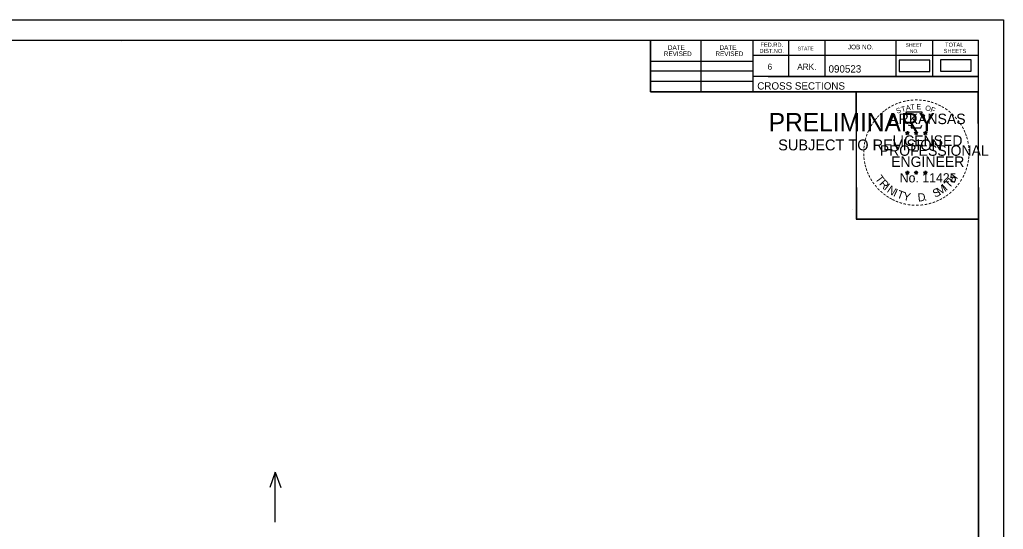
# Model space of a CAD drawing. Extents: x 1406028 to 1412453, y 321733 to 325986.
# Drawn here: x 1411758.3 to 1411946.2, y 322587.7 to 322684.9 of the extents above; entities that cross this region are included whole.
import ezdxf

# ---------------------------------------------------------------- set-up
doc = ezdxf.new("R2010")
doc.units = 0
for name, color, linetype in [('R_Border', 7, 'Continuous'), ('R_Border PE', 7, 'Continuous'), ('R_Border Prem', 7, 'Continuous'), ('R_Fin Surface', 7, 'Continuous'), ('R_No Plot', 7, 'Continuous'), ('R_Water Annot', 7, 'Continuous')]:
    doc.layers.add(name, color=color, linetype=linetype)

msp = doc.modelspace()

# ---------------------------------------------------------------- linework, layer by layer
at = {"layer": 'R_Border'}
for p, q in [((1411625.24, 322681.05), (1411941.42, 322681.05)), ((1411777.76, 322680.79), (1411777.76, 322680.79)), ((1411777.76, 322680.79), (1411777.76, 322680.79)), ((1411878.78, 322671.17), (1411878.78, 322681.05)), ((1411888.46, 322671.17), (1411888.46, 322681.05)), ((1411898.32, 322681.05), (1411898.32, 322671.17)), ((1411905.16, 322681.05), (1411905.16, 322674.11)), ((1411912.1, 322681.05), (1411912.1, 322674.11)), ((1411925.68, 322681.05), (1411925.68, 322674.11)), ((1411932.62, 322681.05), (1411932.62, 322674.11)), ((1411941.42, 322475.59), (1411941.42, 322681.05)), ((1411878.78, 322677.03), (1411898.32, 322677.03)), ((1411941.42, 322678.11), (1411898.32, 322678.11)), ((1411941.42, 322678.13), (1411941.42, 322678.13)), ((1411878.78, 322675.17), (1411898.32, 322675.17)), ((1411878.78, 322673.23), (1411898.32, 322673.23)), ((1411941.42, 322674.11), (1411898.32, 322674.11)), ((1411901.28, 322674.11), (1411941.42, 322674.11)), ((1411941.42, 322671.17), (1411878.78, 322671.17))]:
    msp.add_line(p, q, dxfattribs=at)
at = {"layer": 'R_Border PE'}
for p, q in [((1411927.51, 322663.42), (1411927.86, 322663.31)), ((1411927.51, 322663.42), (1411927.76, 322663.38)), ((1411927.51, 322663.42), (1411927.75, 322663.3)), ((1411927.86, 322663.68), (1411927.82, 322663.43)), ((1411927.86, 322663.31), (1411927.86, 322663.68)), ((1411927.86, 322663.68), (1411927.91, 322663.43)), ((1411928.2, 322663.42), (1411927.86, 322663.31)), ((1411928.2, 322663.42), (1411927.92, 322663.37)), ((1411928.2, 322663.42), (1411928, 322663.32)), ((1411929.18, 322663.42), (1411929.53, 322663.31)), ((1411929.18, 322663.42), (1411929.43, 322663.38)), ((1411929.18, 322663.42), (1411929.42, 322663.3)), ((1411929.53, 322663.68), (1411929.49, 322663.43)), ((1411929.53, 322663.31), (1411929.53, 322663.68)), ((1411929.53, 322663.68), (1411929.58, 322663.43)), ((1411929.87, 322663.42), (1411929.53, 322663.31)), ((1411929.87, 322663.42), (1411929.59, 322663.37)), ((1411929.87, 322663.42), (1411929.67, 322663.32)), ((1411930.94, 322663.41), (1411931.29, 322663.3)), ((1411930.94, 322663.41), (1411931.2, 322663.37)), ((1411930.94, 322663.41), (1411931.18, 322663.29)), ((1411931.29, 322663.67), (1411931.25, 322663.41)), ((1411931.29, 322663.3), (1411931.29, 322663.67)), ((1411931.29, 322663.67), (1411931.34, 322663.42)), ((1411931.64, 322663.41), (1411931.29, 322663.3)), ((1411931.64, 322663.41), (1411931.35, 322663.36)), ((1411931.64, 322663.41), (1411931.43, 322663.31)), ((1411927.64, 322663.02), (1411927.86, 322663.31)), ((1411927.64, 322663.02), (1411927.77, 322663.26)), ((1411927.64, 322663.02), (1411927.86, 322663.23)), ((1411928.07, 322663.02), (1411927.86, 322663.31)), ((1411928.07, 322663.02), (1411927.86, 322663.23)), ((1411928.07, 322663.02), (1411927.93, 322663.31)), ((1411929.31, 322663.02), (1411929.53, 322663.31)), ((1411929.31, 322663.02), (1411929.44, 322663.26)), ((1411929.31, 322663.02), (1411929.53, 322663.23)), ((1411929.74, 322663.02), (1411929.53, 322663.31)), ((1411929.74, 322663.02), (1411929.53, 322663.23)), ((1411929.74, 322663.02), (1411929.6, 322663.31)), ((1411931.08, 322663), (1411931.29, 322663.3)), ((1411931.08, 322663), (1411931.2, 322663.25)), ((1411931.08, 322663), (1411931.29, 322663.22)), ((1411931.5, 322663), (1411931.29, 322663.3)), ((1411931.5, 322663), (1411931.29, 322663.22)), ((1411931.5, 322663), (1411931.37, 322663.29)), ((1411927.5, 322655.85), (1411927.85, 322655.74)), ((1411927.5, 322655.85), (1411927.76, 322655.81)), ((1411927.5, 322655.85), (1411927.74, 322655.73)), ((1411927.85, 322656.1), (1411927.81, 322655.85)), ((1411927.85, 322655.74), (1411927.85, 322656.1)), ((1411927.85, 322656.1), (1411927.9, 322655.85)), ((1411928.2, 322655.85), (1411927.85, 322655.74)), ((1411928.2, 322655.85), (1411927.91, 322655.8)), ((1411928.2, 322655.85), (1411928, 322655.75)), ((1411929.17, 322655.85), (1411929.52, 322655.74)), ((1411929.17, 322655.85), (1411929.43, 322655.81)), ((1411929.17, 322655.85), (1411929.41, 322655.73)), ((1411929.52, 322656.1), (1411929.48, 322655.85)), ((1411929.52, 322655.74), (1411929.52, 322656.1)), ((1411929.52, 322656.1), (1411929.57, 322655.85)), ((1411929.87, 322655.85), (1411929.52, 322655.74)), ((1411929.87, 322655.85), (1411929.58, 322655.8)), ((1411929.87, 322655.85), (1411929.67, 322655.75)), ((1411930.94, 322655.84), (1411931.29, 322655.73)), ((1411930.94, 322655.84), (1411931.19, 322655.8)), ((1411930.94, 322655.84), (1411931.18, 322655.72)), ((1411931.29, 322656.09), (1411931.25, 322655.84)), ((1411931.29, 322655.73), (1411931.29, 322656.09)), ((1411931.29, 322656.09), (1411931.34, 322655.84)), ((1411931.64, 322655.84), (1411931.29, 322655.73)), ((1411931.64, 322655.84), (1411931.35, 322655.79)), ((1411931.64, 322655.84), (1411931.43, 322655.74)), ((1411927.64, 322655.44), (1411927.85, 322655.74)), ((1411927.64, 322655.44), (1411927.76, 322655.69)), ((1411927.64, 322655.44), (1411927.85, 322655.66)), ((1411928.07, 322655.44), (1411927.85, 322655.74)), ((1411928.07, 322655.44), (1411927.85, 322655.66)), ((1411928.07, 322655.44), (1411927.93, 322655.73)), ((1411929.31, 322655.44), (1411929.52, 322655.74)), ((1411929.31, 322655.44), (1411929.43, 322655.69)), ((1411929.31, 322655.44), (1411929.52, 322655.66)), ((1411929.74, 322655.44), (1411929.52, 322655.74)), ((1411929.74, 322655.44), (1411929.52, 322655.66)), ((1411929.74, 322655.44), (1411929.6, 322655.73)), ((1411931.07, 322655.43), (1411931.29, 322655.73)), ((1411931.07, 322655.43), (1411931.2, 322655.68)), ((1411931.07, 322655.43), (1411931.29, 322655.65)), ((1411931.5, 322655.43), (1411931.29, 322655.73)), ((1411931.5, 322655.43), (1411931.29, 322655.65)), ((1411931.5, 322655.43), (1411931.37, 322655.72))]:
    msp.add_line(p, q, dxfattribs=at)
for points in [[(1411927.55, 322667.3), (1411927.82, 322666.47)], [(1411931.06, 322666.38), (1411931.2, 322666.66), (1411930.52, 322666.64), (1411930.67, 322667.3), (1411927.55, 322667.3)], [(1411927.86, 322663.68), (1411928.07, 322663.02), (1411927.51, 322663.42), (1411928.2, 322663.42), (1411927.64, 322663.02), (1411927.86, 322663.68)], [(1411928.04, 322664.88), (1411928.04, 322664.79), (1411928.6, 322664.77), (1411928.55, 322664.3), (1411930.42, 322664.3), (1411930.62, 322664.84)], [(1411929.53, 322663.68), (1411929.74, 322663.02), (1411929.18, 322663.42), (1411929.87, 322663.42), (1411929.31, 322663.02), (1411929.53, 322663.68)], [(1411931.29, 322663.67), (1411931.5, 322663), (1411930.94, 322663.41), (1411931.64, 322663.41), (1411931.08, 322663), (1411931.29, 322663.67)], [(1411927.85, 322656.1), (1411928.07, 322655.44), (1411927.5, 322655.85), (1411928.2, 322655.85), (1411927.64, 322655.44), (1411927.85, 322656.1)], [(1411929.52, 322656.1), (1411929.74, 322655.44), (1411929.17, 322655.85), (1411929.87, 322655.85), (1411929.31, 322655.44), (1411929.52, 322656.1)], [(1411931.29, 322656.09), (1411931.5, 322655.43), (1411930.94, 322655.84), (1411931.64, 322655.84), (1411931.07, 322655.43), (1411931.29, 322656.09)]]:
    msp.add_lwpolyline(points, dxfattribs=at)
for centre, radius in [((1411927.86, 322663.31), 0.172), ((1411927.86, 322663.31), 0.145), ((1411927.86, 322663.31), 0.116), ((1411927.86, 322663.31), 0.0991), ((1411927.86, 322663.31), 0.0747), ((1411927.86, 322663.31), 0.0495), ((1411929.53, 322663.31), 0.172), ((1411929.53, 322663.31), 0.145), ((1411929.53, 322663.31), 0.116), ((1411929.53, 322663.31), 0.0991), ((1411929.53, 322663.31), 0.0747), ((1411929.53, 322663.31), 0.0495), ((1411931.29, 322663.3), 0.172), ((1411931.29, 322663.3), 0.145), ((1411931.29, 322663.3), 0.116), ((1411931.29, 322663.3), 0.0991), ((1411931.29, 322663.3), 0.0747), ((1411931.29, 322663.3), 0.0495), ((1411927.86, 322663.31), 0.0296), ((1411929.53, 322663.31), 0.0296), ((1411931.29, 322663.3), 0.0296), ((1411927.85, 322655.74), 0.172), ((1411927.85, 322655.74), 0.145), ((1411927.85, 322655.74), 0.116), ((1411927.85, 322655.74), 0.0991), ((1411929.52, 322655.74), 0.172), ((1411929.52, 322655.74), 0.145), ((1411929.52, 322655.74), 0.116), ((1411929.52, 322655.74), 0.0991), ((1411931.29, 322655.73), 0.172), ((1411931.29, 322655.73), 0.145), ((1411931.29, 322655.73), 0.116), ((1411927.85, 322655.74), 0.0747), ((1411927.85, 322655.74), 0.0495), ((1411927.85, 322655.74), 0.0296), ((1411929.52, 322655.74), 0.0747), ((1411929.52, 322655.74), 0.0495), ((1411929.52, 322655.74), 0.0296), ((1411931.29, 322655.73), 0.0991), ((1411931.29, 322655.73), 0.0747), ((1411931.29, 322655.73), 0.0495), ((1411931.29, 322655.73), 0.0296)]:
    msp.add_circle(centre, radius, dxfattribs=at)
at = {"layer": 'R_Fin Surface'}
for points in [[(1411926.28, 322675.03), (1411932.11, 322675.03), (1411932.11, 322677.21), (1411926.28, 322677.21)], [(1411934.19, 322675.11), (1411940.02, 322675.11), (1411940.02, 322677.29), (1411934.19, 322677.29)]]:
    msp.add_lwpolyline(points, close=True, dxfattribs=at)
at = {"layer": 'R_No Plot'}
for p, q in [((1411612.84, 322684.94), (1411946.18, 322684.94)), ((1411917.46, 322648.71), (1411917.46, 322648.71))]:
    msp.add_line(p, q, dxfattribs=at)
for points in [[(1411612.84, 322684.94), (1411946.18, 322684.94), (1411946.18, 322471.61), (1411612.84, 322471.61)], [(1411859.16, 322681.05), (1411878.78, 322681.05), (1411878.78, 322671.17), (1411894.9, 322671.17), (1411918.1, 322671.17), (1411918.1, 322646.84), (1411941.42, 322646.84), (1411941.42, 322475.59), (1411625.24, 322475.59), (1411625.24, 322681.05)], [(1411918.1, 322671.17), (1411941.3, 322671.17), (1411941.42, 322646.84), (1411918.22, 322646.84)]]:
    msp.add_lwpolyline(points, close=True, dxfattribs=at)
at = {"layer": 'R_Water Annot'}
for p, q in [((1411807.14, 322598.6), (1411806.08, 322595.67)), ((1411807.14, 322589.03), (1411807.14, 322598.6)), ((1411807.14, 322598.6), (1411808.21, 322595.67))]:
    msp.add_line(p, q, dxfattribs=at)

# ---------------------------------------------------------------- texts
at = {"layer": 'R_Border'}
for s, height, p in [('FED.RD.', 0.782, (1411899.8, 322679.77)), ('SHEET', 0.684, (1411927.54, 322679.77)), ('TOTAL', 0.782, (1411935.06, 322679.77)), ('REVISED', 0.879, (1411881.34, 322678)), ('DATE', 0.879, (1411882.12, 322679.18)), ('REVISED', 0.879, (1411891.2, 322678)), ('DATE', 0.879, (1411891.98, 322679.18)), ('DIST.NO.', 0.782, (1411899.6, 322678.59)), ('STATE', 0.684, (1411906.92, 322679.09)), ('JOB NO.', 0.879, (1411916.5, 322679.29)), ('NO.', 0.684, (1411928.32, 322678.59)), ('SHEETS', 0.782, (1411934.78, 322678.59)), ('6', 1.17, (1411901.16, 322675.37)), ('ARK.', 1.172, (1411906.82, 322675.37)), ('090523', 1.4, (1411912.8, 322674.85)), ('CROSS SECTIONS', 1.4, (1411899.19, 322671.6))]:
    msp.add_text(s, height=height, rotation=360, dxfattribs=at).set_placement(p)
at = {"layer": 'R_Border PE'}
for s, height, rotation, p in [('-', 1.6, 24.3072, (1411925.66, 322668.16)), ('-', 1.6, 19.1761, (1411926.3, 322668.43)), ('-', 1.6, 13.6301, (1411927.05, 322668.67)), ('-', 1.6, 10.2193, (1411927.73, 322668.83)), ('-', 1.6, 5.8968, (1411928.45, 322668.94)), ('-', 1.6, 0.1862, (1411929.23, 322669.01)), ('-', 1.6, 357.743, (1411929.95, 322669)), ('-', 1.6, 352.1617, (1411930.69, 322668.94)), ('-', 1.6, 347.2049, (1411931.41, 322668.83)), ('-', 1.6, 342.3362, (1411932.05, 322668.68)), ('-', 1.6, 337.8551, (1411932.78, 322668.45)), ('-', 1.6, 42.9622, (1411922.95, 322666.28)), ('-', 1.6, 38.9507, (1411923.38, 322666.7)), ('-', 1.6, 36.2317, (1411923.86, 322667.08)), ('-', 1.6, 34.0636, (1411924.43, 322667.47)), ('-', 1.6, 28.7918, (1411925.03, 322667.84)), ('S', 1, 21.594, (1411925.9, 322666.98)), ('T', 1, 16.4036, (1411926.82, 322667.31)), ('A', 1, 11.2132, (1411927.64, 322667.56)), ('T', 1, 6.0228, (1411928.49, 322667.73)), ('E', 1, 0.8323, (1411929.6, 322667.84)), ('O', 1, 350.4515, (1411931.2, 322667.63)), ('F', 1, 340.0707, (1411932.16, 322667.4)), ('-', 1.6, 334.1211, (1411933.41, 322668.18)), ('-', 1.6, 329.6409, (1411933.99, 322667.9)), ('-', 1.6, 325.8627, (1411934.64, 322667.54)), ('-', 1.6, 320.5297, (1411935.25, 322667.11)), ('-', 1.6, 54.2325, (1411921.68, 322664.75)), ('-', 1.6, 50.6142, (1411922.1, 322665.32)), ('-', 1.6, 48.423, (1411922.5, 322665.8)), ('ARKANSAS', 2, 360, (1411924.4, 322665.01)), ('-', 1.6, 315.5786, (1411935.84, 322666.62)), ('-', 1.6, 309.8797, (1411936.41, 322666.07)), ('-', 1.6, 306.6522, (1411936.94, 322665.47)), ('-', 1.6, 67.7743, (1411920.79, 322663)), ('-', 1.6, 62.8713, (1411921.04, 322663.61)), ('-', 1.6, 58.0706, (1411921.36, 322664.22)), ('-', 1.4, 303.6753, (1411937.42, 322664.9)), ('-', 1.6, 299.6684, (1411937.74, 322664.3)), ('-', 1.6, 294.6628, (1411938.07, 322663.68)), ('-', 1.6, 81.2013, (1411920.24, 322660.94)), ('-', 1.6, 75.461, (1411920.37, 322661.66)), ('-', 1.6, 72.3945, (1411920.57, 322662.37)), ('LICENSED', 2, 360, (1411925, 322660.86)), ('DWB', 0.01, 360, (1411927.84, 322663.31)), ('DWB', 0.01, 360, (1411929.51, 322663.31)), ('DWB', 0.01, 360, (1411931.28, 322663.3)), ('-', 1.6, 290.5728, (1411938.32, 322663.11)), ('-', 1.6, 285.1233, (1411938.56, 322662.53)), ('-', 1.6, 280.5493, (1411938.76, 322661.79)), ('-', 1.6, 89.0622, (1411920.14, 322659.55)), ('-', 1.6, 85.1863, (1411920.16, 322660.25)), ('PROFESSIONAL', 2, 360, (1411922.58, 322658.96)), ('-', 1.6, 276.5962, (1411938.92, 322661.02)), ('-', 1.6, 274.3301, (1411938.98, 322660.3)), ('-', 1.6, 94.1959, (1411920.17, 322658.83)), ('-', 1.6, 98.9479, (1411920.24, 322658.16)), ('-', 1.6, 101.7149, (1411920.38, 322657.43)), ('ENGINEER', 2, 360, (1411924.76, 322656.84)), ('-', 1.6, 260.9953, (1411938.92, 322658.34)), ('-', 1.6, 263.5172, (1411939, 322659)), ('-', 1.6, 269.9407, (1411939.01, 322659.66)), ('-', 1.6, 105.4578, (1411920.54, 322656.83)), ('-', 1.6, 109.0874, (1411920.76, 322656.2)), ('-', 1.6, 114.0643, (1411921.01, 322655.6)), ('-', 1.6, 247.8887, (1411938.41, 322656.27)), ('-', 1.6, 252.8681, (1411938.63, 322656.95)), ('-', 1.6, 255.7626, (1411938.81, 322657.67)), ('-', 1.6, 115.7289, (1411921.31, 322654.99)), ('-', 1.6, 120.4471, (1411921.67, 322654.4)), ('-', 1.6, 125.8934, (1411922.07, 322653.84)), ('T', 1.54, 306.0406, (1411921.61, 322654.58)), ('R', 1.54, 314.005, (1411922.38, 322653.53)), ('No. 11425', 1.757, 360, (1411926.39, 322653.88)), ('DWB', 0.01, 360, (1411927.84, 322655.73)), ('DWB', 0.01, 360, (1411929.51, 322655.74)), ('DWB', 0.01, 360, (1411931.28, 322655.73)), ('T', 1.54, 46.6444, (1411935.84, 322652.67)), ('H', 1.54, 54.6088, (1411936.73, 322653.61)), ('-', 1.6, 239.0712, (1411937.75, 322654.89)), ('-', 1.6, 244.6197, (1411938.15, 322655.64)), ('-', 1.6, 130.7181, (1411922.54, 322653.29)), ('-', 1.6, 134.2238, (1411923.05, 322652.74)), ('-', 1.6, 138.9338, (1411923.58, 322652.28)), ('I', 1.54, 321.9694, (1411923.28, 322652.6)), ('N', 1.54, 326.5002, (1411923.84, 322652.13)), ('I', 1.54, 335.3603, (1411925.05, 322651.34)), ('T', 1.54, 339.8912, (1411925.71, 322651.01)), ('S', 1.54, 26.9312, (1411933.16, 322650.94)), ('M', 1.54, 32.6563, (1411934, 322651.35)), ('I', 1.54, 42.1136, (1411935.28, 322652.19)), ('-', 1.6, 221.0851, (1411935.92, 322652.6)), ('-', 1.6, 225.7653, (1411936.44, 322653.11)), ('-', 1.6, 231.2538, (1411936.92, 322653.67)), ('-', 1.6, 233.8452, (1411937.35, 322654.24)), ('-', 1.6, 144.6463, (1411924.13, 322651.87)), ('-', 1.6, 148.0898, (1411924.7, 322651.5)), ('-', 1.6, 151.5704, (1411925.27, 322651.18)), ('-', 1.6, 154.6002, (1411925.8, 322650.93)), ('-', 1.6, 158.5612, (1411926.42, 322650.67)), ('Y', 1.54, 347.8556, (1411926.93, 322650.57)), ('D', 1.54, 6.3969, (1411929.91, 322650.21)), ('.', 1.54, 13.7642, (1411931.11, 322650.34)), ('-', 1.6, 200.7184, (1411933.04, 322650.8)), ('-', 1.6, 204.2516, (1411933.66, 322651.08)), ('-', 1.6, 207.3568, (1411934.28, 322651.39)), ('-', 1.6, 212.2491, (1411934.84, 322651.74)), ('-', 1.6, 215.7363, (1411935.37, 322652.13)), ('-', 1.6, 162.7983, (1411927.11, 322650.46)), ('-', 1.6, 167.5555, (1411927.82, 322650.3)), ('-', 1.6, 173.1155, (1411928.59, 322650.19)), ('-', 1.6, 176.5183, (1411929.34, 322650.13)), ('-', 1.6, 181.5918, (1411930.09, 322650.15)), ('-', 1.6, 185.8167, (1411930.9, 322650.23)), ('-', 1.6, 191.2858, (1411931.63, 322650.36)), ('-', 1.6, 195.4743, (1411932.36, 322650.56))]:
    msp.add_text(s, height=height, rotation=rotation, dxfattribs=at).set_placement(p)
at = {"layer": 'R_Border Prem'}
for s, height, p in [('PRELIMINARY', 3.5, (1411901.38, 322663.63)), ('DWB', 0.01, (1411902.12, 322665.48)), ('SUBJECT TO REVISION', 2.0751, (1411903.18, 322660))]:
    msp.add_text(s, height=height, rotation=360, dxfattribs=at).set_placement(p)

doc.saveas('drawing.dxf')
